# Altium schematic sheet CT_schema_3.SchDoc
size 297 x 247 mm
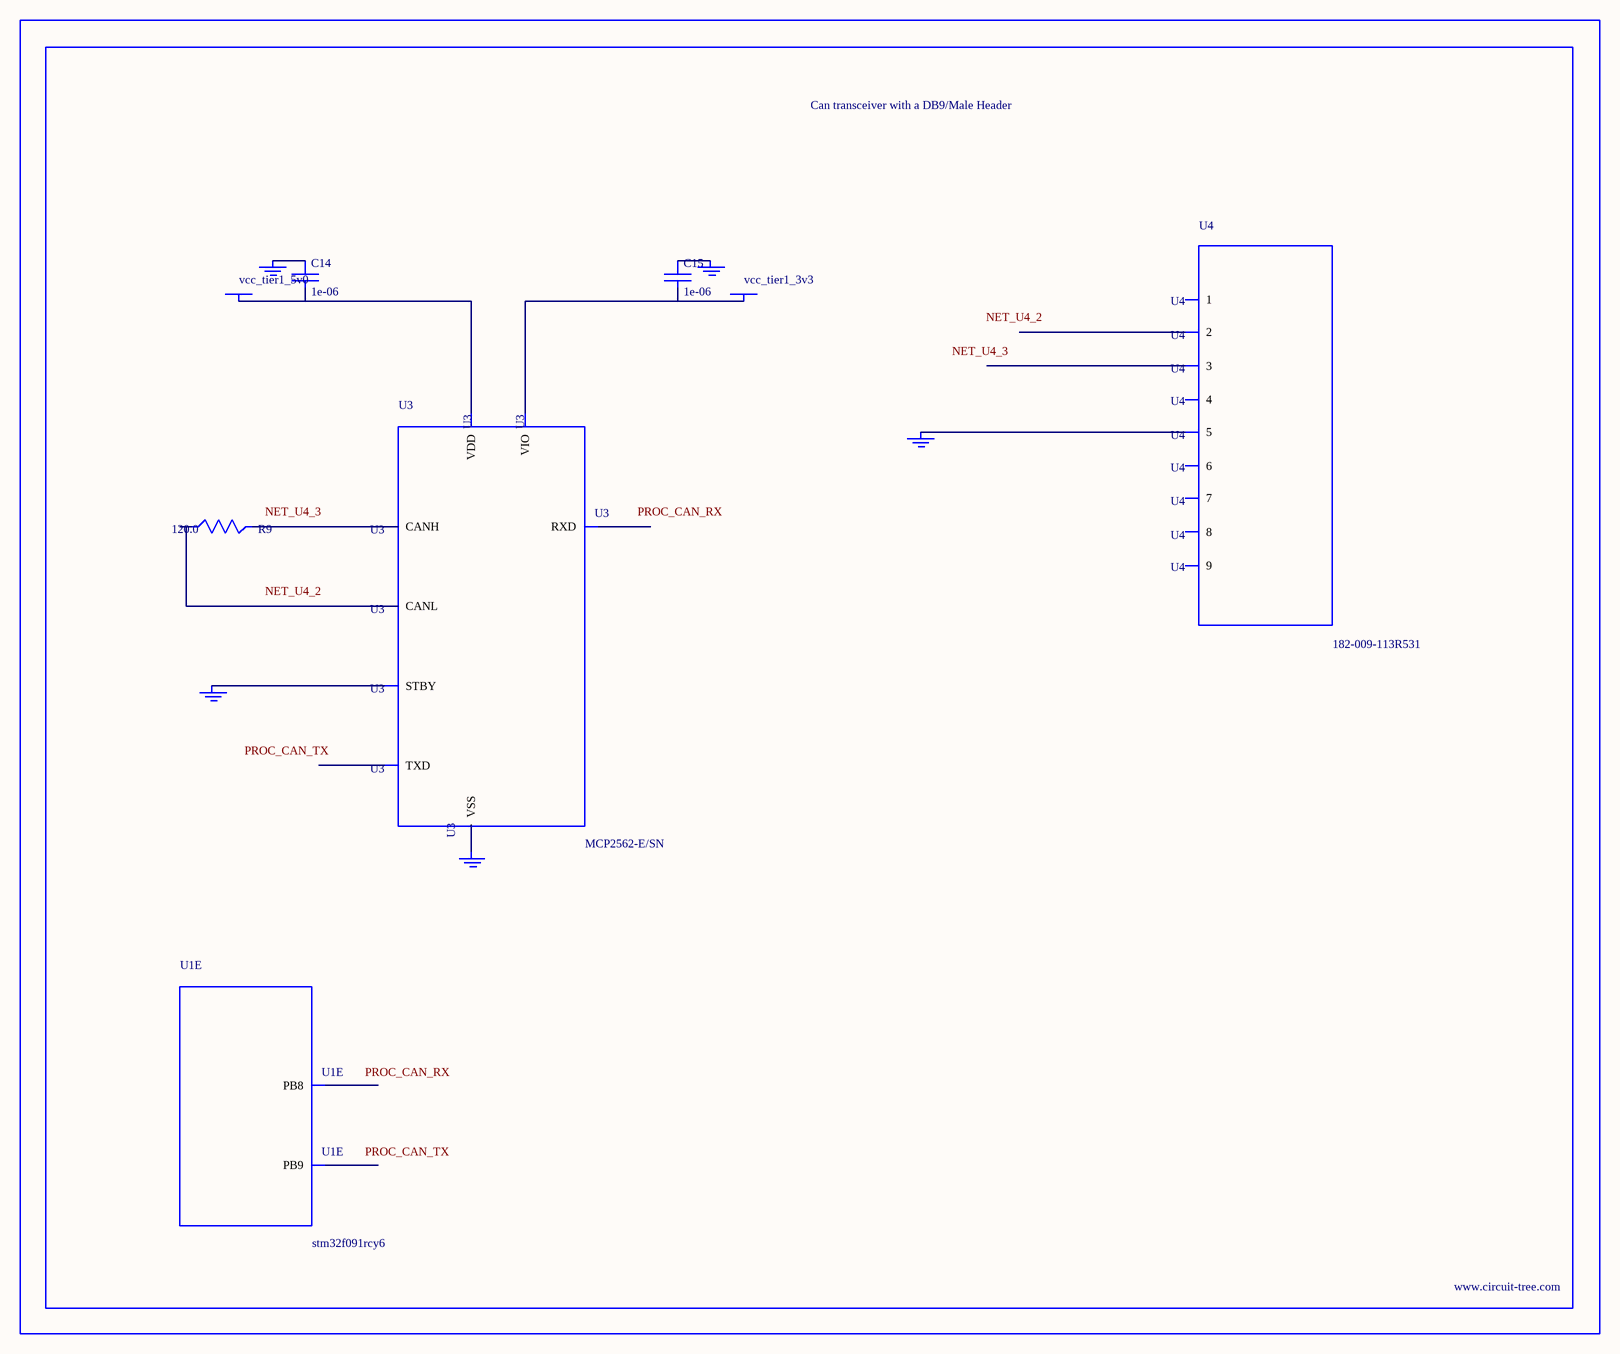
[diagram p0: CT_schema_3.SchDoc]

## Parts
BORDER2  (no value)
C14  1e-06  [C0603]
C15  1e-06  [C0603]
GND_INSTANCE_2_0  (no value)
GND_INSTANCE_2_1  (no value)
GND_INSTANCE_2_2  (no value)
GND_INSTANCE_2_3  (no value)
GND_INSTANCE_2_4  (no value)
POWER_INSTANCE_2_0  vcc_tier1_5v0
POWER_INSTANCE_2_1  vcc_tier1_3v3
R9  120.0  [R0603]
U1  stm32f091rcy6  [WLCSP64]  (part E of 8)
U3  MCP2562-E/SN  [SOIC-8]
U4  182-009-113R531  [182-009-MALE]

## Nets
NetC14_1: C14.1 GND_INSTANCE_2_0.0(GND)
NetC14_2: C14.2 POWER_INSTANCE_2_0.0(PWR) U3.3(VDD)
NetC15_1: C15.1 GND_INSTANCE_2_1.0(GND)
NetC15_2: C15.2 POWER_INSTANCE_2_1.0(PWR) U3.5(VIO)
NetGND_INSTANCE_2_2_0: GND_INSTANCE_2_2.0(GND) U3.8(STBY)
NetGND_INSTANCE_2_3_0: GND_INSTANCE_2_3.0(GND) U3.2(VSS)
NetGND_INSTANCE_2_4_0: GND_INSTANCE_2_4.0(GND) U4.5
NetR9_1: R9.1 U3.6(CANL)
NetR9_2: R9.2 U3.7(CANH)

Not connected (* = marked no-connect by the designer): U1 A6(PB8) B6(PB9); U3 1(TXD) 4(RXD); U4 1 2 3 4 6 7 8 9

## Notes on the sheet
- Labels drawn without touching a wire or pin: NET_U4_2, NET_U4_3, PROC_CAN_RX, PROC_CAN_TX

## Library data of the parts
BORDER2 = BORDER_PAGE2
C14 C15 = C0603C105K3RACTU
GND_INSTANCE_2_0-GND_INSTANCE_2_4 = GND
POWER_INSTANCE_2_0 POWER_INSTANCE_2_1 = PWR
R9 = RC0603JR-07120RL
